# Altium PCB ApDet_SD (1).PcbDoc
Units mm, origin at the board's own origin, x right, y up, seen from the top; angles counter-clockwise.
Board outline 60.5 x 60.5 mm, 2 copper layers (Top Layer, Bottom Layer); 31 components, 40 nets, 234 pads, 38 vias.
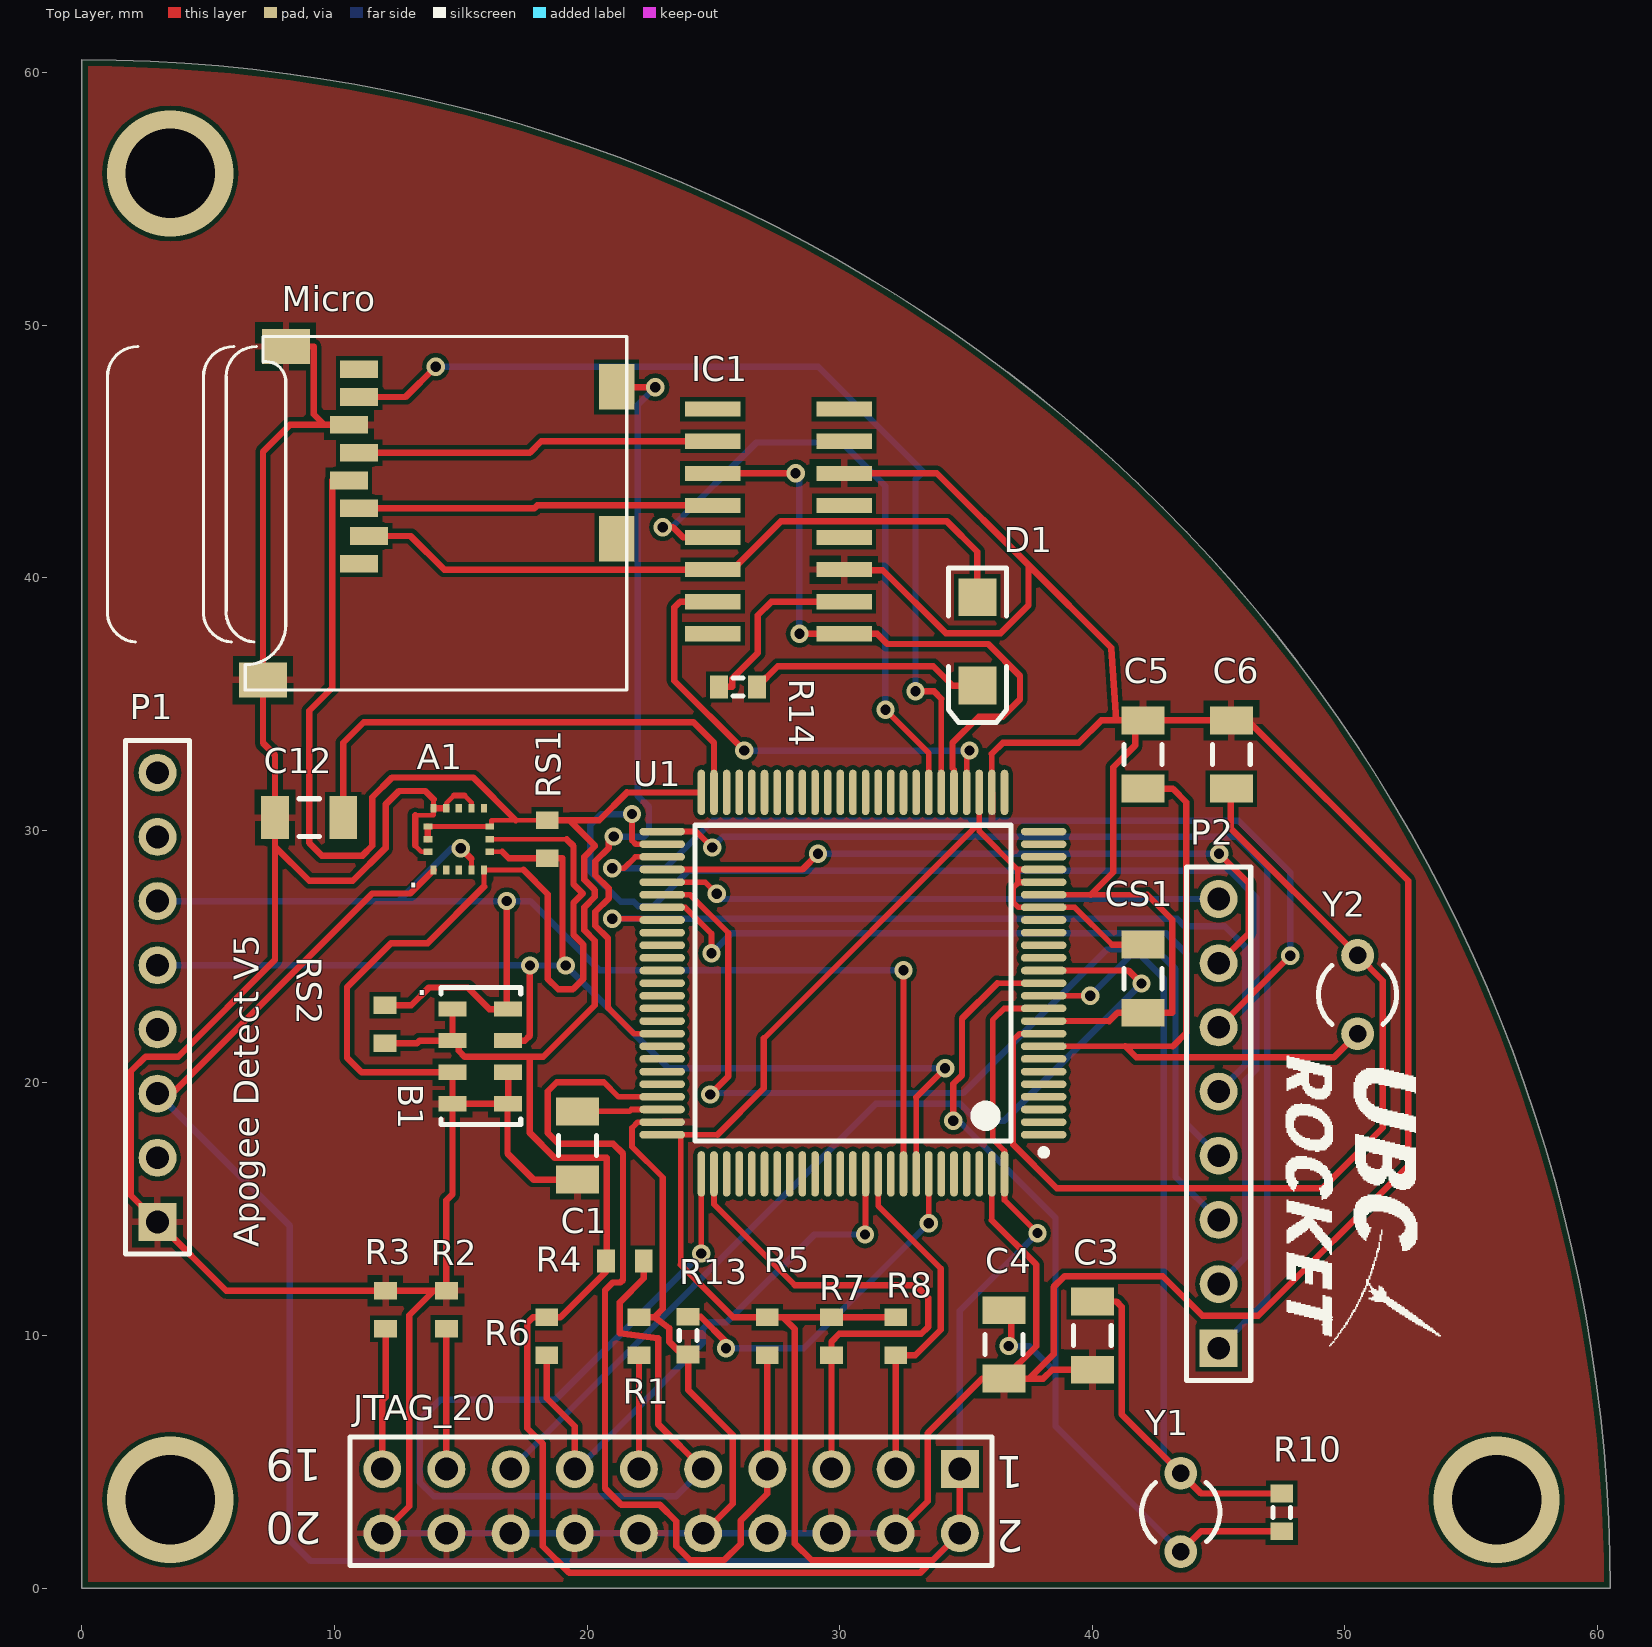
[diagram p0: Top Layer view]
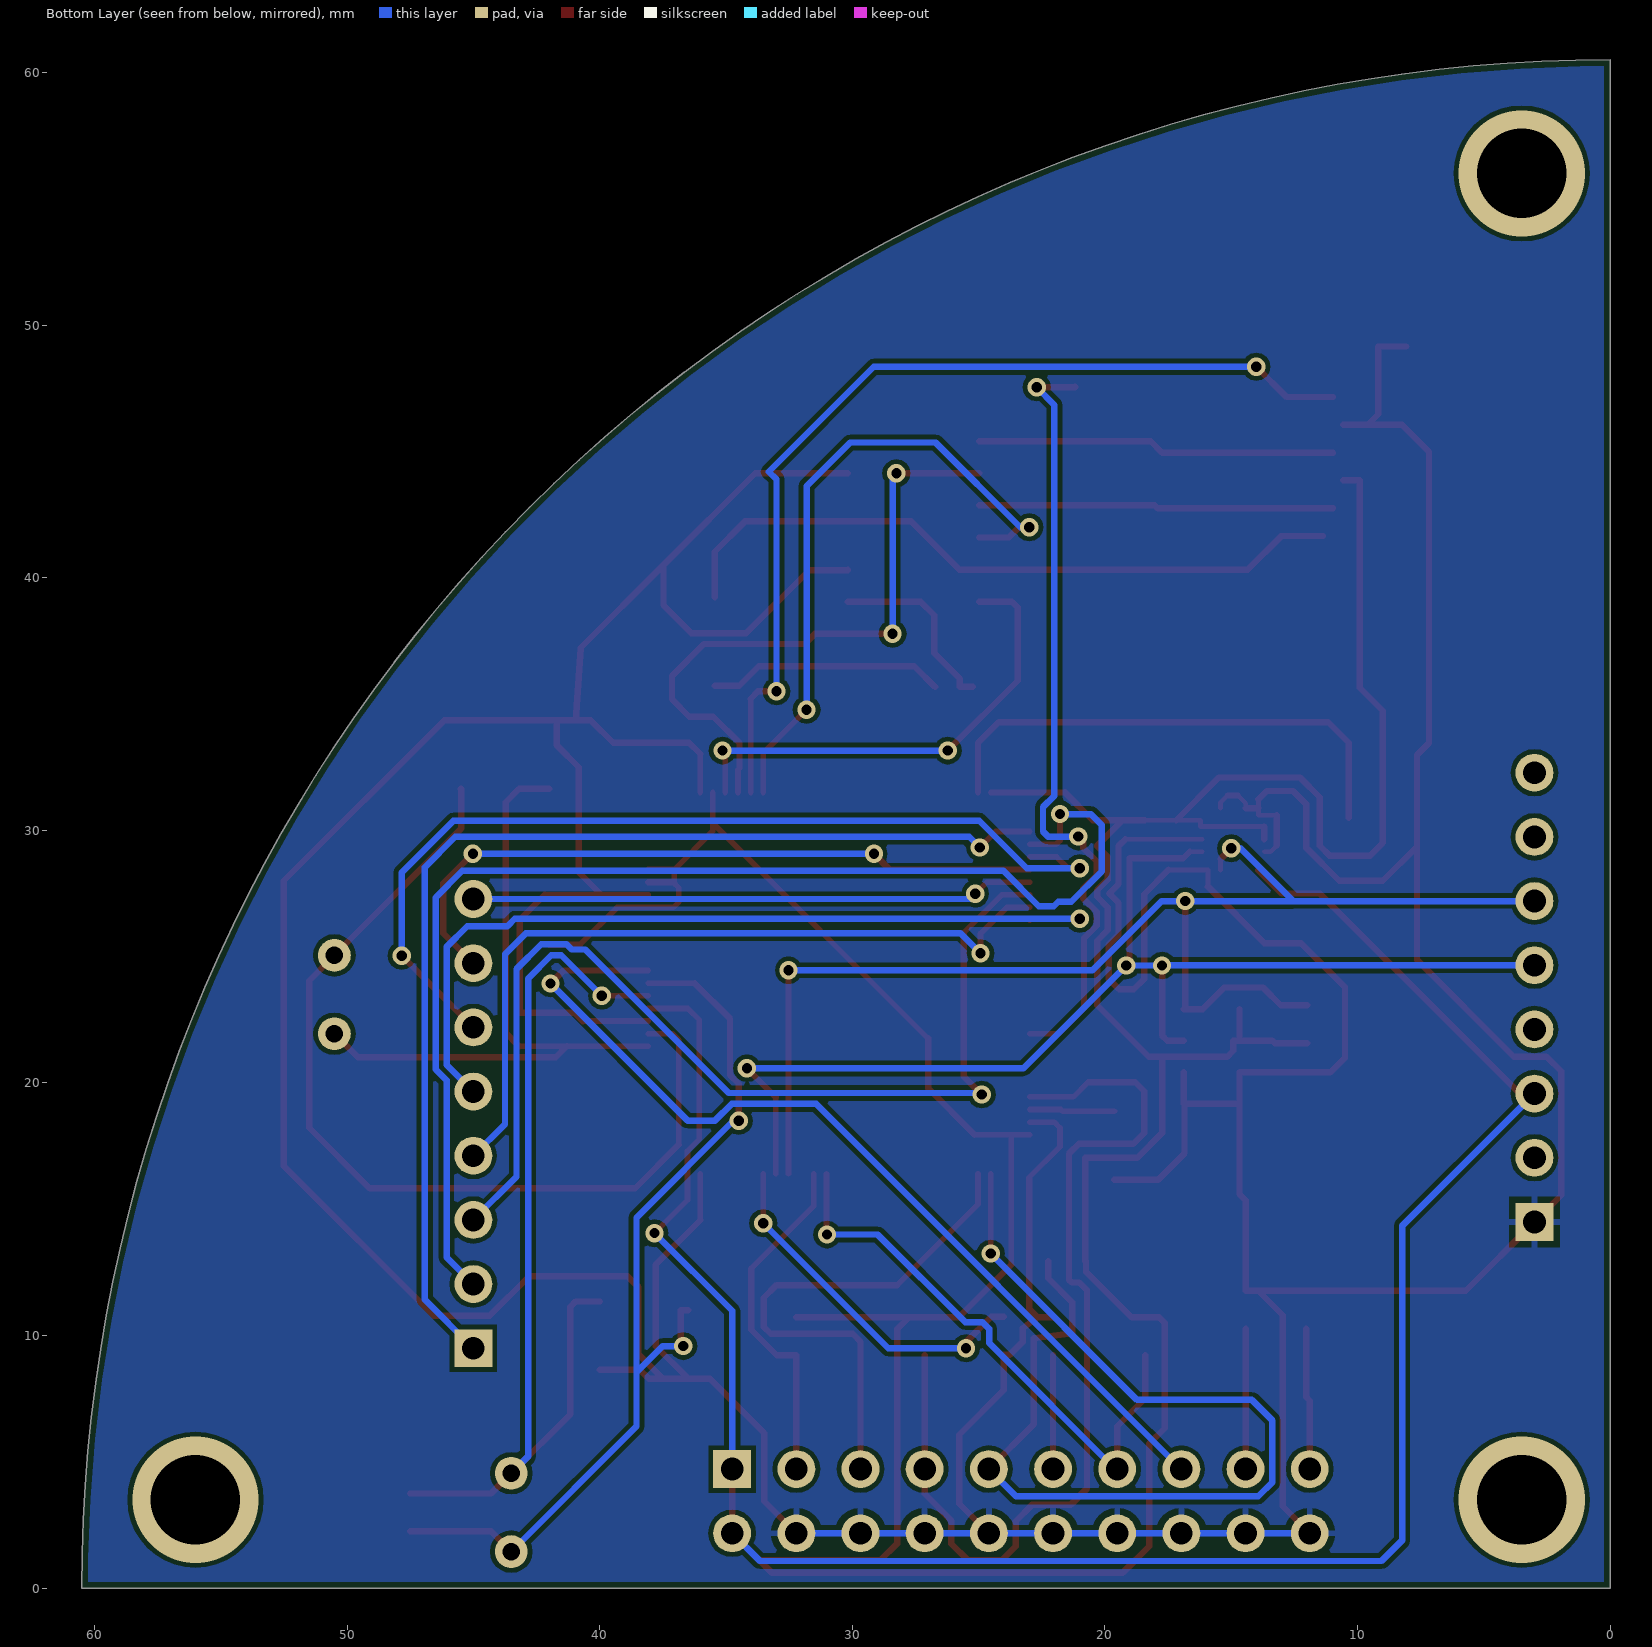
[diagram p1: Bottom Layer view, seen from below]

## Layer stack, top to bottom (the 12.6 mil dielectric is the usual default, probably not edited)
Top Solder: solder mask 0.0102, Solder Resist, Dk 3.5
Top Layer: signal copper 0.0356
Dielectric 1: dielectric 0.32, FR-4, Dk 4.8
Bottom Layer: signal copper 0.0356
Bottom Solder: solder mask 0.0102, Solder Resist, Dk 3.5

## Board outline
0,60.5 cw(c0,0) 60.5,0 0,0

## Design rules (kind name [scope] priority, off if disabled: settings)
BoardOutlineClearance [All] p1: gap=0.254 ignorepadtopadclearanceinfootprint=FALSE except(0: Arc-SplitContinuation Track-SplitContinuation SMDPad-SplitContinuation THPad-SplitContinuation Via-SplitContinuation Fill-SplitContinuation Poly-SplitContinuation Region-SplitContinuation Text-SplitContinuation)
Clearance [All] p1: gap=0.18 ignorepadtopadclearanceinfootprint=FALSE
HoleSize [All] p1: absolutevalues=TRUE maxlimit=5.08 minlimit=0.025 maxpercent=80.000 minpercent=20.000
HoleToHoleClearance [All] p1: gap=0.178 allowstackedmicrovias=TRUE
MinimumSolderMaskSliver [All] p1: minsoldermaskwidth=0.025
PolygonConnect [All] p1: connectstyle=Relief reliefconductorwidth=0.254 reliefentries=4 polygonreliefangle="90 Angle" airgapwidth=0.254
RoutingVias [All] p1: holewidth=0.406 width=0.725 viastyle="Through Hole" minholewidth=0.406 minwidth=0.725 maxholewidth=0.406 maxwidth=0.725
SMDNeckDown [All] p1: percent=75.000
SilkToSilkClearance [All] p1: silktosilkclearance=0.178
SilkToSolderMaskClearance [IsPad] p1: minsilkscreentomaskgap=0.076 clearancetoexposedcopper=TRUE
SolderMaskExpansion [All] p1: expansion=0.102
Width [All] p1: maxlimit=0.254 minlimit=0.178 preferedwidth=0.254
25 further rules are at their usual default settings.

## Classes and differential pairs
component class Sensors: A1 B1 CS1 RS1 RS2
component class apogee_detection_board: C1 C3 C4 C5 C6 C12 D1 IC1 JTAG_20 Micro P1 P2 R1 R2 R3 R4 R5 R6 R7 R8 R10 R13 R14 U1 Y1 Y2

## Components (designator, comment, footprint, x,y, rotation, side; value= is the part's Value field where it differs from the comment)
A1 "LIS331HH Accelerometer" LGA16 13.925,28.425 r90 top
B1 "MS5607-02BA Barometer" "Barometer LCC" 15.175,22.925 r270 top
C1 "Cap Semi" C1206 19.625,17.525 r270 top value=100nF
C3 "Cap Semi" C1206 40,10 r90 top value=22pF
C4 "Cap Semi" C1206 36.5,9.65 r90 top value=22pF
C5 "Cap Semi" C1206 42,33 r270 top value=22pF
C6 "Cap Semi" C1206 45.5,33 r270 top value=22pF
C12 "Cap Semi" C1206 9,30.5 r180 top value=100nF
CS1 "Cap Semi" C1206 42,24.125 r90 top value=100nF
D1 "LED2" 3.2X1.6X1.1 35.45,37.475 r270 top
IC1 "4050D" SO16 27.575,42.225 r270 top
JTAG_20 "JTAG-20" PCBComponent_1 34.755,4.715 r180 top
Micro "" MICROSD 21.615,49.55 r270 top
P1 "Header 8" HDR1X8 3,14.5 r90 top
P2 "Header 8" HDR1X8 45,9.5 r90 top
R1 "RTCK PD" J1-0603 22.055,9.975 r270 top value=10K
R2 "DBGRQ PD" J1-0603 14.435,11.025 r270 top value=10K
R3 "DBGACK PD" J1-0603 12.025,11.025 r270 top value=10K
R4 "RTCK PD" J1-0603 21.5,12.95 r180 top value=10K
R5 "RTCK PD" J1-0603 27.135,9.975 r90 top value=10K
R6 "RTCK PD" J1-0603 18.4,9.975 r90 top value=10K
R7 "RTCK PD" J1-0603 29.675,9.975 r90 top value=10K
R8 "RTCK PD" J1-0603 32.215,9.975 r90 top value=10K
R10 "RTCK PD" J1-0603 47.5,3 r90 top value=1M
R13 "RTCK PD" J1-0603 24,10 r90 top value=100K
R14 "DBGRQ PD" J1-0603 25.975,35.675 r180 top value=1K
RS1 "Res3" J1-0603 18.425,29.65 r90 top value=1K
RS2 "Res3" J1-0603 12,22.325 r270 top value=1K
U1 "STM32F417VET6" STM-LQFP100_N 30.525,23.95 r180 top
Y1 "XTAL" R38 43.5,3 r180 top
Y2 "XTAL" R38 50.5,23.5 r0 top

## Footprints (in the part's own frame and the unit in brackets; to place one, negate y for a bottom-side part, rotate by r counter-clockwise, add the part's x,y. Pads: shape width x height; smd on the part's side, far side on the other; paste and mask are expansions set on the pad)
3.2X1.6X1.1 [mm] "SMT LED; 2 Flat Leads"
  rect 1.5x1.5 smd: 1(-1.75,0) 2(1.75,0)
  silkscreen extent -2.9,-1.15 3.2,1.15
"Barometer LCC" [mm]
  rect 0.6x1.1 smd: 1(0,-0.5) 2(1.25,-0.5) 3(2.5,-0.5) 4(3.75,-0.5) 5(3.75,1.7) 6(2.5,1.7) 7(1.25,1.7) 8(0,1.7)
  silkscreen extent -0.85,-0.95 4.58,2.2
C1206 [mm] "Chip Capacitor, Body 3.2x1.6mm, IPC High Density"
  rect 1.1x1.7 smd: 1(-1.35,0) 2(1.35,0)
  silkscreen extent -0.4,-0.75 0.4,0.75, body extent -1.7,-0.9 1.7,0.9, height 1.3
HDR1X8 [mm] "Connector; Header; 8 Position"
  rect 1.5x1.5 hole 0.9: 1(0,0)
  round 1.5 hole 0.9: 2(2.54,0) 3(5.08,0) 4(7.62,0) 5(10.16,0) 6(12.7,0) 7(15.24,0) 8(17.78,0)
  silkscreen extent -1.27,-1.27 19.05,1.27
J1-0603 [mm] "Chip Resistor, Body 1.6x0.8mm, IPC High Density"
  rect 0.7x0.9 smd: 1(-0.75,0) 2(0.75,0)
  body extent -0.85,-0.48 0.85,0.48, height 0.9
LGA16 [mm]
  rect 0.35x0.25 smd: 1(0,0) 2(0,-0.5) 3(0,-1) 4(0,-1.5) 5(0,-2) 9(2.45,-2) 10(2.45,-1.5) 11(2.45,-1) 12(2.45,-0.5) 13(2.45,0)
  rect 0.25x0.35 smd: 6(0.725,-2.225) 7(1.225,-2.225) 8(1.725,-2.225) 14(1.725,0.225) 15(1.225,0.225) 16(0.725,0.225)
MICROSD [mm]
  rect 0.7x1.5 smd: 1(9,-10.64) 2(7.9,-10.24) 3(6.8,-10.64) 4(5.7,-11.04) 5(4.6,-10.64) 6(3.5,-11.04) 7(2.4,-10.64) 8(1.3,-10.64)
  rect 1.8x1.4 smd: CD1(2,-0.44) CD2(8,-0.44)
  rect 1.4x1.9 smd: MT1(0.4,-13.54) MT2(13.6,-14.44)
  silkscreen extent 0,-20.6 14,-0.04
PCBComponent_1 [mm]
  rect 1.5x1.5 hole 0.9: 1(0,0)
  round 1.5 hole 0.9: 2(0,2.54) 3(2.54,0) 4(2.54,2.54) 5(5.08,0) 6(5.08,2.54) 7(7.62,0) 8(7.62,2.54) 9(10.16,0) 10(10.16,2.54) 11(12.7,0) 12(12.7,2.54) 13(15.24,0) 14(15.24,2.54) 15(17.78,0) 16(17.78,2.54) 17(20.32,0) 18(20.32,2.54) 19(22.86,0) 20(22.86,2.54)
  silkscreen extent -1.27,-1.27 24.13,3.81
R38 [mm] "Crystal, Thru-Hole; 2 Leads; Body 3.1 x 8.2 mm (Dia.xH)"
  round 1.3 hole 0.7: 1(0,1.55) 2(0,-1.55)
  silkscreen extent -1.55,-1.19 1.55,1.17
SO16 [mm]
  rect 0.6x2.2 smd: 1(-4.445,-2.6) 2(-3.175,-2.6) 3(-1.905,-2.6) 4(-0.635,-2.6) 5(0.635,-2.6) 6(1.905,-2.6) 7(3.175,-2.6) 8(4.445,-2.6) 9(4.445,2.6) 10(3.175,2.6) 11(1.905,2.6) 12(0.635,2.6) 13(-0.635,2.6) 14(-1.905,2.6) 15(-3.175,2.6) 16(-4.445,2.6)
STM-LQFP100_N [mm] "Thin QFP, 100-Leads, Body 14x14mm, Pitch 0.5mm, IPC Medium Density"
  oval 1.8x0.3 smd: 1(-7.55,6) 2(-7.55,5.5) 3(-7.55,5) 4(-7.55,4.5) 5(-7.55,4) 6(-7.55,3.5) 7(-7.55,3) 8(-7.55,2.5) 9(-7.55,2) 10(-7.55,1.5) 11(-7.55,1) 12(-7.55,0.5) 13(-7.55,0) 14(-7.55,-0.5) 15(-7.55,-1) 16(-7.55,-1.5) 17(-7.55,-2) 18(-7.55,-2.5) 19(-7.55,-3) 20(-7.55,-3.5) 21(-7.55,-4) 22(-7.55,-4.5) 23(-7.55,-5) 24(-7.55,-5.5) 25(-7.55,-6) 51(7.55,-6) 52(7.55,-5.5) 53(7.55,-5) 54(7.55,-4.5) 55(7.55,-4) 56(7.55,-3.5) 57(7.55,-3) 58(7.55,-2.5) 59(7.55,-2) 60(7.55,-1.5) 61(7.55,-1) 62(7.55,-0.5) 63(7.55,0) 64(7.55,0.5) 65(7.55,1) 66(7.55,1.5) 67(7.55,2) 68(7.55,2.5) 69(7.55,3) 70(7.55,3.5) 71(7.55,4) 72(7.55,4.5) 73(7.55,5) 74(7.55,5.5) 75(7.55,6)
  oval 0.3x1.8 smd: 26(-6,-7.55) 27(-5.5,-7.55) 28(-5,-7.55) 29(-4.5,-7.55) 30(-4,-7.55) 31(-3.5,-7.55) 32(-3,-7.55) 33(-2.5,-7.55) 34(-2,-7.55) 35(-1.5,-7.55) 36(-1,-7.55) 37(-0.5,-7.55) 38(0,-7.55) 39(0.5,-7.55) 40(1,-7.55) 41(1.5,-7.55) 42(2,-7.55) 43(2.5,-7.55) 44(3,-7.55) 45(3.5,-7.55) 46(4,-7.55) 47(4.5,-7.55) 48(5,-7.55) 49(5.5,-7.55) 50(6,-7.55) 76(6,7.55) 77(5.5,7.55) 78(5,7.55) 79(4.5,7.55) 80(4,7.55) 81(3.5,7.55) 82(3,7.55) 83(2.5,7.55) 84(2,7.55) 85(1.5,7.55) 86(1,7.55) 87(0.5,7.55) 88(0,7.55) 89(-0.5,7.55) 90(-1,7.55) 91(-1.5,7.55) 92(-2,7.55) 93(-2.5,7.55) 94(-3,7.55) 95(-3.5,7.55) 96(-4,7.55) 97(-4.5,7.55) 98(-5,7.55) 99(-5.5,7.55) 100(-6,7.55)
  silkscreen extent -7.68,-6.25 6.25,6.82, body extent -7,-7 7,7, height 1.6

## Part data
C1 C3 C4 C5 C6 C12 CS1: "Capacitor (Semiconductor SIM Model)"
D1: "Typical RED, GREEN, YELLOW, AMBER GaAs LED"
IC1: "Hex non-inverting BUFFER"
JTAG_20: library part "HEADER 10X2", "20-pin JTAG header"
Micro: library part MICROSD
P1 P2: "Header, 8-Pin"
R1 R2 R3 R4 R5 R6 R7 R8 R10 R13 R14: library part Res3, "Resistor"
RS1 RS2: "Resistor"
U1: "ARM Cortex-M4 32-bit MCU+FPU, 210 DMIPS, 512 kB Flash, 192 kB Internal RAM, 82 I/Os, 100-pin LQFP, -40 to 85 degC, Tray", I/Os (High Current)=82, Manufacturer=STMicroelectronics, Operating Frequency(F) (Processor speed) (MHz)=168, Supplier Part Number 1=497-11901-ND, Supply Voltage(Vcc) max (V)=3.6, Supply Voltage(Vcc) min (V)=1.8
Y1 Y2: "Crystal Oscillator"

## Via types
v1: diameter 0.725, hole 0.406, Top Layer to Bottom Layer, 35 vias
v2: diameter 5, hole 3.54, Top Layer to Bottom Layer, 3 vias

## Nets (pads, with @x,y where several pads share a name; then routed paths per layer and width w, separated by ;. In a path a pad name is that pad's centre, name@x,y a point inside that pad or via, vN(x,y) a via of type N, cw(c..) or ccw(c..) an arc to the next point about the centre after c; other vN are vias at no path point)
3.3V: A1.1 A1.8 A1.14 A1.15 B1.1 B1.2 CS1.2 JTAG_20.1 JTAG_20.2 Micro.4 P1.3 R4.2 R5.2 R6.2 R7.2 R8.2 RS1.2 RS2.2 U1.11 U1.19 U1.21 U1.22 U1.28 U1.50 U1.75 U1.100 | length 247.4
  Top Layer w0.188: A1.14 A1.8 16.215,30.15 16.215,30.4 17.18,30.4 RS1.2
  Top Layer w0.225: 21.58,31.5 U1.50 ; U1.75 U1.75@23.708,17.95 ; 23.708,12.808 U1.75@23.708,17.95 ; 25.163,17.95 U1.75@23.708,17.95 ; 27,21.762 35.525,30.287 ; U1.28 35.525,30.287 ; v1(37.831,14.057) 36.525,15.362 U1.100 36.525,17.309 36.053,17.781 36.053,22.489 36.513,22.95 U1.11 ; U1.22 37.043,28.45 ; 40.779,25.475 39.304,26.95 U1.19 37.078,26.95 36.865,27.163 36.865,27.721 37.043,27.899 37.043,28.45 ; 35.525,30.287 35.525,29.968 37.043,28.45
  Top Layer w0.254: P1.3 3.58,19.58 11.5,27.5 13,27.5 A1.1 ; Micro.4 9.916,43.85 9.916,35.647 9,34.731 9,29.5 9.5,29 11.114,29 11.5,29.386 11.5,31.312 12.278,32.091 15.49,32.091 17.18,30.4 ; RS2.2 13.269,21.575 13.369,21.675 B1.2 ; A1.15 A1.14 ; B1.1 B1.2 ; RS1.2 19.303,30.4 ; 21.58,31.5 20.48,30.4 19.303,30.4 ; 23.708,12.808 25.791,10.725 R5.2 27.751,10.725 ; 25.163,17.95 27,19.787 27,21.762 ; R8.2 30.922,10.725 R7.2 27.751,10.725 ; JTAG_20.1 JTAG_20.2 33.683,1.103 ; 37.043,27.899 37.094,27.95 U1.21 ; 40.779,25.475 CS1.2 ; B1.2 14.92,21.675 14.92,21.27 15.148,21.042 17.739,21.042 ; 17.739,21.042 17.739,18.019 18.726,17.032 20.787,17.032 20.787,12.95 R4.2 20.75,12.529 18.946,10.725 R6.2 17.862,10.725 17.638,10.501 17.638,6.335 18.247,5.725 18.247,1.661 19.289,0.62 33.2,0.62 33.683,1.103 ; 17.739,21.042 18.273,21.042 20.305,23.074 20.305,25.635 19.897,26.043 19.897,26.957 20.305,27.365 20.305,27.635 19.897,28.043 19.897,28.957 20.305,29.365 20.305,29.398 19.303,30.4 ; 27.751,10.725 28.229,10.247 28.229,1.763 28.89,1.103 33.683,1.103
  Bottom Layer w0.254: P1.3 8.24,14.34 8.24,1.89 9.052,1.077 33.657,1.077 JTAG_20.2 ; JTAG_20.1 34.755,10.981 v1(37.831,14.057)
5V: P1.2
ACT1: P2.1 U1.51 | length 44.7
  Top Layer w0.225: U1.51 24.325,29.95 v1(24.953,29.322)
  Bottom Layer w0.254: v1(24.953,29.322) 25.377,29.747 45.712,29.747 46.928,28.53 46.928,11.428 P2.1
ACT2: P2.2 U1.52 | length 49.8
  Top Layer w0.225: v1(21.782,30.643) 21.782,29.598 21.93,29.45 U1.52
  Bottom Layer w0.254: v1(21.782,30.643) 20.559,30.643 20.127,30.211 20.127,28.373 21.331,27.17 21.853,27.17 22.022,27 22.616,27 24.014,28.398 45.434,28.398 46.494,27.339 46.494,20.536 46.06,20.102 46.06,13.1 P2.2
"ACT 24V": P1.4
CD: Micro.CD1 U1.67 | length 31.4
  Top Layer w0.225: 20.854,22.956 21.86,21.95 U1.67
  Top Layer w0.254: 20.854,22.956 20.83,22.98 20.83,25.723 20.331,26.223 20.331,26.777 20.854,27.301 20.854,27.699 20.331,28.223 20.331,28.777 20.854,29.301 20.854,29.554 v1(21.053,29.753) ; Micro.CD1 21.175,47.534 v1(22.703,47.534)
  Bottom Layer w0.254: v1(21.053,29.753) 22.253,29.753 22.452,29.952 22.452,30.92 22,31.372 22,46.831 v1(22.703,47.534)
CLK: IC1.3 IC1.9 U1.30 | length 25.4
  Top Layer w0.225: 34.464,33.462 34.464,32.461 34.525,32.4 U1.30
  Top Layer w0.254: IC1.3 v1(28.255,44.13) ; v1(28.407,37.78) IC1.9 31.481,37.78 31.887,37.374 35.875,37.374 37.138,36.111 37.138,35.189 36.449,34.5 35.502,34.5 34.464,33.462
  Bottom Layer w0.254: v1(28.255,44.13) 28.407,43.978 v1(28.407,37.78)
CS: IC1.7 U1.29 | length 19
  Top Layer w0.225: U1.29 35.025,33.044 v1(35.138,33.157)
  Top Layer w0.254: IC1.7 23.683,39.05 23.454,38.821 23.454,35.926 v1(26.223,33.157)
  Bottom Layer w0.254: v1(26.223,33.157) v1(35.138,33.157)
GND: A1.5 A1.7 A1.10 A1.12 A1.13 A1.16 B1.3 B1.4 B1.5 B1.6 C1.2 C3.1 C4.1 C5.1 C6.1 C12.2 CS1.1 IC1.11 IC1.14 JTAG_20.4 JTAG_20.6 JTAG_20.8 JTAG_20.10 JTAG_20.12 JTAG_20.14 JTAG_20.16 JTAG_20.18 JTAG_20.20 Micro.6 Micro.MT1 Micro.MT2 P1.1 R1.1 R2.1 R3.1 R13.1 U1.10 U1.20 U1.27 U1.74 U1.99 | length 294.6
  Top Layer w0.188: 13.193,29.398 13.441,29.15 A1.16 ; 13.193,30.592 13.925,30.592 A1.13 13.925,31.227 ; A1.12 14.425,31.062 14.742,31.379 ; 15.148,31.379 15.425,31.103 A1.10 ; 15.925,27.773 A1.5 15.925,28.433 17.485,28.433 ; A1.7 19.189,29.65
  Top Layer w0.225: U1.74 22.006,18.45 21.778,18.222 21.778,17.474 23,16.252 ; 36.025,14.567 U1.99 ; U1.27 36.025,33.025 ; U1.10 40.674,22.45 ; U1.20 39.939,27.45 42.174,27.45
  Top Layer w0.254: Micro.MT1 9.179,49.15 9.179,46.467 9.596,46.05 ; Micro.6 9.596,46.05 ; JTAG_20.20 12.964,3.244 12.964,10.81 13.929,11.775 ; 13.193,29.398 13.193,30.592 ; A1.13 A1.12 ; 13.925,31.227 13.595,31.557 12.558,31.557 12.024,31.024 12.024,29.297 10.728,28 9.003,28 7.65,29.353 ; 14.742,31.379 15.148,31.379 ; 15.925,27.773 13.69,25.537 12.253,25.537 10.5,23.785 10.5,21 11.075,20.425 B1.3 B1.4 ; B1.6 B1.5 B1.5@16.85,19.175 ; 17.485,28.433 18.45,27.468 18.45,24.115 18.857,23.709 19.441,23.709 19.847,24.115 19.847,25.478 19.463,25.863 19.463,27.137 19.826,27.5 19.463,27.863 19.463,29.377 19.189,29.65 ; C1.2 17.881,16.175 16.85,17.206 B1.5@16.85,19.175 ; R1.1 22.667,10.725 ; 23,16.252 23,11.058 22.667,10.725 ; JTAG_20.10 25.766,3.346 25.766,6.081 24,7.847 R13.1 23.761,9.25 23.246,9.765 23.246,10.299 22.667,10.725 ; IC1.11 30.175,40.295 31.705,40.295 34.192,37.808 36.375,37.808 37.473,38.905 37.473,40.5 ; IC1.14 33.843,44.13 37.473,40.5 ; JTAG_20.4 33.487,3.447 33.487,6.141 35.646,8.3 C4.1 ; 36.025,14.567 37.78,12.812 37.78,9.58 C4.1 ; 36.025,33.025 36.462,33.462 39.462,33.462 40.35,34.35 40.955,34.35 ; 39.939,27.45 40.828,28.339 40.828,32.497 41.691,33.361 C5.1@41.691,34.35 ; C3.1 38.409,8.65 38.059,8.3 37.5,8.3 ; 40.674,22.45 40.999,22.775 CS1.1 43.165,22.775 43.165,26.459 42.174,27.45 ; 7.65,29.353 7.65,24.872 3.82,21.042 2.525,21.042 1.94,20.457 1.94,15.56 P1.1 5.725,11.775 R3.1 13.218,11.775 13.929,11.775 ; 7.65,29.353 C12.2 7.65,32.98 7.175,33.455 Micro.MT2 7.173,35.95 7.173,44.983 8.24,46.05 9.596,46.05 ; 13.929,11.775 R2.1 14.435,15.352 14.675,15.592 B1.4 ; B1.4 B1.5@16.85,19.175 ; C4.1 37.5,8.3 ; 37.473,40.5 40.752,37.221 40.955,34.35 ; 37.5,8.3 38.466,9.265 38.466,11.923 38.897,12.355 42.784,12.355 44.358,10.78 46.568,10.78 52.5,16.712 52.5,28 46.15,34.35 C6.1 C5.1 C5.1@41.691,34.35 ; 40.955,34.35 C5.1@41.691,34.35
  Bottom Layer w0.254: JTAG_20.20 JTAG_20.18 JTAG_20.16 JTAG_20.14 JTAG_20.12 JTAG_20.10 JTAG_20.8 JTAG_20.6 JTAG_20.4
IG1: P2.3 U1.56 | length 41.9
  Top Layer w0.225: U1.56 24.082,27.45 25.597,25.935
  Top Layer w0.254: v1(24.877,19.543) 25.597,20.263 25.597,25.935
  Bottom Layer w0.254: v1(24.877,19.543) 24.937,19.604 34.894,19.604 40.574,25.283 41.107,25.283 41.313,25.489 42.31,25.489 43.292,24.507 43.292,16.288 P2.3
"IG1 OUT": P2.4 U1.57 | length 31.1
  Top Layer w0.225: U1.57 23.886,26.95 24.927,25.909
  Top Layer w0.254: v1(24.927,25.131) 24.927,25.909
  Bottom Layer w0.254: v1(24.927,25.131) 25.719,25.923 42.918,25.923 43.749,25.092 43.749,18.371 P2.4
"IG1 TEST": P2.5 U1.58 | length 33.7
  Top Layer w0.225: v1(21,26.5) 22.925,26.5 U1.58
  Bottom Layer w0.254: v1(21,26.5) 43.356,26.5 43.652,26.204 45.241,26.204 46.06,25.385 46.06,20.72 P2.5
IG2: P2.6 U1.53 | length 37.9
  Top Layer w0.225: v1(21,28.5) 21.464,28.5 21.914,28.95 U1.53
  Top Layer w0.254: P2.6 v1(47.838,25.038)
  Bottom Layer w0.254: v1(21,28.5) 23.089,28.5 24.971,30.382 45.788,30.382 47.838,28.331 v1(47.838,25.038)
"IG2 OUT": P2.7 U1.54 | length 27.6
  Top Layer w0.225: U1.54 28.526,28.45
  Top Layer w0.254: 28.526,28.45 v1(29.144,29.068) ; P2.7 46.187,25.927 46.187,27.9 v1(45.019,29.068)
  Bottom Layer w0.254: v1(29.144,29.068) v1(45.019,29.068)
"IG2 TEST": P2.8 U1.55 | length 22.3
  Top Layer w0.225: U1.55 24.674,27.95 v1(25.131,27.493)
  Bottom Layer w0.254: v1(25.131,27.493) 25.344,27.28 P2.8
MISO: Micro.7 U1.31 | length 38.2
  Top Layer w0.225: U1.31 34.025,35.21
  Top Layer w0.254: Micro.7 12.814,47.15 v1(14.011,48.347) ; v1(33,35.5) 33.735,35.5 34.025,35.21
  Bottom Layer w0.254: v1(14.011,48.347) 29.153,48.347 33.301,44.198 33,43.897 v1(33,35.5)
MOSI: IC1.5 U1.32 | length 25.9
  Top Layer w0.225: v1(31.811,34.77) 33.525,33.056 U1.32
  Top Layer w0.254: v1(23,42) 23.4,42 23.81,41.59 IC1.5
  Bottom Layer w0.254: v1(23,42) 23.356,42 26.705,45.349 30.084,45.349 31.811,43.622 v1(31.811,34.77)
NetC1_1: C1.1 U1.73 | length 3.4
  Top Layer w0.225: C1.1 21.678,18.875 21.753,18.95 U1.73
NetC3_2: C3.2 R10.2 U1.12 Y1.2 | length 38.8
  Top Layer w0.225: U1.12 v1(39.913,23.45)
  Top Layer w0.254: C3.2 40.955,11.35 41.158,11.147 41.158,6.892 Y1.2 44.3,3.75 R10.2
  Bottom Layer w0.254: v1(39.913,23.45) 41.518,25.055 41.911,25.055 42.834,24.131 42.834,5.216 Y1.2
NetC4_2: C4.2 R10.1 U1.13 Y1.1 | length 37.3
  Top Layer w0.225: 36.243,23.95 U1.13
  Top Layer w0.254: v1(34.5,18.5) 34.5,19.965 34.843,20.307 34.843,22.549 36.243,23.95 ; C4.2 36.789,11 36.789,9.688 v1(36.688,9.586) ; Y1.1 44.3,2.25 R10.1
  Bottom Layer w0.254: v1(34.5,18.5) 34.708,18.5 38.542,14.666 38.542,8.545 ; v1(36.688,9.586) 37.5,9.586 38.542,8.545 ; Y1.1 38.542,6.408 38.542,8.545
NetC5_2: C5.2 U1.8 Y2.2 | length 26.7
  Top Layer w0.225: U1.8 41.31,21.45 43.19,21.45
  Top Layer w0.254: 41.31,21.45 41.744,21.016 49.566,21.016 Y2.2 ; C5.2 43.19,31.65 43.723,31.117 43.723,21.983 43.19,21.45
NetC6_2: C6.2 U1.9 Y2.1 | length 37.7
  Top Layer w0.225: 36.865,17.562 36.865,21.696 37.119,21.95 U1.9
  Top Layer w0.254: 36.865,17.562 38.593,15.835 49.108,15.835 51.5,18.226 51.5,24.05 Y2.1 45.476,30.074 45.476,31.65 C6.2
NetC12_1: C12.1 U1.49 | length 20.3
  Top Layer w0.225: U1.49 25.025,33.462
  Top Layer w0.254: C12.1 10.35,33.462 11.163,34.275 24.212,34.275 25.025,33.462
NetD1_1: D1.1 IC1.6 Micro.2 | length 27.7
  Top Layer w0.254: Micro.2 13.015,41.65 14.345,40.32 IC1.6 25.766,40.32 27.671,42.225 34.249,42.225 35.45,41.024 D1.1
NetD1_2: D1.2 R14.1 | length 9.4
  Top Layer w0.254: R14.1 27.55,36.5 33.704,36.5 34.479,35.725 D1.2
NetIC1_2: IC1.2 Micro.5 | length 14.2
  Top Layer w0.254: Micro.5 17.739,44.95 18.189,45.4 IC1.2
NetIC1_4: IC1.4 Micro.3 | length 14
  Top Layer w0.254: Micro.3 17.917,42.75 18.027,42.86 IC1.4
NetIC1_10: IC1.10 R14.2 | length 7.4
  Top Layer w0.254: R14.2 25.74,35.675 25.74,36.002 26.756,37.018 26.756,38.508 27.298,39.05 IC1.10
NetJTAG_20_3: JTAG_20.3 R8.1 U1.90 | length 13.9
  Top Layer w0.225: U1.90 31.525,15.13 34,12.655
  Top Layer w0.254: JTAG_20.3 32.215,6.945 R8.1 32.997,9.225 34,10.228 34,12.655
NetJTAG_20_5: JTAG_20.5 R7.1 U1.77 | length 21.5
  Top Layer w0.225: U1.77 25.025,15.2 28.225,12
  Top Layer w0.254: 28.225,12 33,12 33.5,11.5 33.5,10.342 33.226,10.068 29.982,10.068 29.675,9.761 R7.1 JTAG_20.5
NetJTAG_20_7: JTAG_20.7 R5.1 U1.72 | length 38.9
  Top Layer w0.225: 20.669,20.026 21.244,19.45 U1.72
  Top Layer w0.254: 20.669,20.026 18.806,20.026 18.45,19.67 18.45,18.019 18.882,17.587 21.041,17.587 21.422,17.206 21.422,12.202 21.321,12.101 21.016,12.101 20.711,11.796 20.711,3.947 21.346,3.312 22.87,3.312 23.53,2.652 23.53,1.661 24.089,1.103 25.418,1.103 26.078,1.763 26.078,2.68 27.135,3.737 JTAG_20.7 R5.1
NetJTAG_20_9: JTAG_20.9 R4.1 U1.76 | length 42.1
  Top Layer w0.225: v1(24.525,13.248) U1.76
  Top Layer w0.254: R4.1 22.25,12.268 21.295,11.313 21.295,10.094 22.812,9.891 22.812,6.498 JTAG_20.9
  Bottom Layer w0.254: v1(24.525,13.248) 18.73,7.453 14.183,7.453 13.37,6.64 13.37,4.201 13.929,3.643 23.523,3.643 JTAG_20.9
NetJTAG_20_11: JTAG_20.11 R1.2 | length 4.5
  Top Layer w0.254: JTAG_20.11 22.055,6.945 R1.2
NetJTAG_20_13: JTAG_20.13 R6.1 U1.89 | length 23
  Top Layer w0.225: v1(31,14) 31.025,14.025 U1.89
  Top Layer w0.254: R6.1 18.4,7.526 19.515,6.411 JTAG_20.13
  Bottom Layer w0.254: JTAG_20.13 19.588,4.715 24.588,9.715 24.588,10.27 24.853,10.535 25.535,10.535 29,14 v1(31,14)
NetJTAG_20_15: JTAG_20.15 U1.14 | length 37.6
  Top Layer w0.225: U1.14 41.433,24.45
  Top Layer w0.254: 41.433,24.45 v1(41.945,23.937)
  Bottom Layer w0.254: JTAG_20.15 31.43,19.17 34.777,19.17 35.435,18.512 36.52,18.512 v1(41.945,23.937)
NetJTAG_20_17: JTAG_20.17 R2.2 | length 5.6
  Top Layer w0.254: JTAG_20.17 R2.2
NetJTAG_20_19: JTAG_20.19 R3.2 | length 5.6
  Top Layer w0.254: JTAG_20.19 11.895,7.427 12.025,7.557 R3.2
NetR13_2: R13.2 U1.94 | length 14.2
  Top Layer w0.225: v1(33.525,14.45) U1.94
  Top Layer w0.254: R13.2 24.5,10.75 25.5,9.75 v1(25.5,9.5)
  Bottom Layer w0.254: v1(25.5,9.5) 28.575,9.5 v1(33.525,14.45)
SCL: A1.4 B1.8 P1.6 RS2.1 U1.92 | length 52.9
  Top Layer w0.188: A1.4 15.425,28.868
  Top Layer w0.225: U1.92 v1(32.525,24.461)
  Top Layer w0.254: RS2.1 13.04,23.075 13.743,23.777 15.283,23.777 16.135,22.925 B1.8@16.825,22.925 ; v1(15,29.293) 15.425,28.868 ; v1(16.825,27.2) B1.8@16.825,22.925 ; B1.8 B1.8@16.825,22.925
  Bottom Layer w0.254: P1.6 12.544,27.2 ; v1(15,29.293) 14.636,29.293 12.544,27.2 ; v1(32.525,24.461) 20.492,24.461 17.753,27.2 v1(16.825,27.2) 12.544,27.2
SDA: A1.6 B1.7 P1.5 RS1.1 U1.93 | length 59.2
  Top Layer w0.188: A1.6 16.647,29.15
  Top Layer w0.225: U1.93 33.025,19.436
  Top Layer w0.254: 16.647,29.15 16.897,28.9 RS1.1 19.029,28.9 19.029,24.781 v1(19.162,24.648) ; B1.7 17.534,21.675 17.739,21.88 v1(17.739,24.648) ; 33.025,19.436 v1(34.173,20.584)
  Bottom Layer w0.254: P1.5 7.046,24.66 ; v1(34.173,20.584) 23.226,20.584 v1(19.162,24.648) v1(17.739,24.648) ; 7.046,24.66 17.728,24.66 v1(17.739,24.648) ; 7.046,24.66 7.057,24.648 v1(17.739,24.648)
pads on no net: A1.2 A1.3 A1.9 A1.11 IC1.1 IC1.8 IC1.12 IC1.13 IC1.15 IC1.16 Micro.1 Micro.8 Micro.CD2 P1.7 P1.8 U1.1 U1.2 U1.3 U1.4 U1.5 U1.6 U1.7 U1.15 U1.16 U1.17 U1.18 U1.23 U1.24 U1.25 U1.26 U1.33 U1.34 U1.35 U1.36 U1.37 U1.38 U1.39 U1.40 U1.41 U1.42 U1.43 U1.44 U1.45 U1.46 U1.47 U1.48 U1.59 U1.60 U1.61 U1.62 U1.63 U1.64 U1.65 U1.66 U1.68 U1.69 U1.70 U1.71 U1.78 U1.79 U1.80 U1.81 U1.82 U1.83 U1.84 U1.85 U1.86 U1.87 U1.88 U1.91 U1.95 U1.96 U1.97 U1.98
copper on no net: | length 0.1
  Top Layer w0: v2@54.95,3.15 v2@55.05,3.25
  other v2: 3.5,3.5 56,3.5 3.5,56

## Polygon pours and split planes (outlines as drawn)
GND on Bottom Layer "bottom" (solid, pour order 24): 0,60.5 cw(c0,0) 60.5,0 0,0
GND on Top Layer "Top Layer-No Net" (solid, pour order 25): 0,60.5 cw(c0,0) 60.5,0 0,0

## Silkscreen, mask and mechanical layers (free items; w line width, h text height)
Top Overlay:
  drawing of 13 lines, arcs and shapes, not listed
  text "." at 12.875,27.725 h1.14
  text "." at 13.225,23.475 h1.14
  text "Apogee Detect V5" at 7,13.5 h1 r90
Mechanical 1:
  lines w0.254: 0,0 58,0 60.299,0 ccw(c0,0) 0,60.299 0,58 0,0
